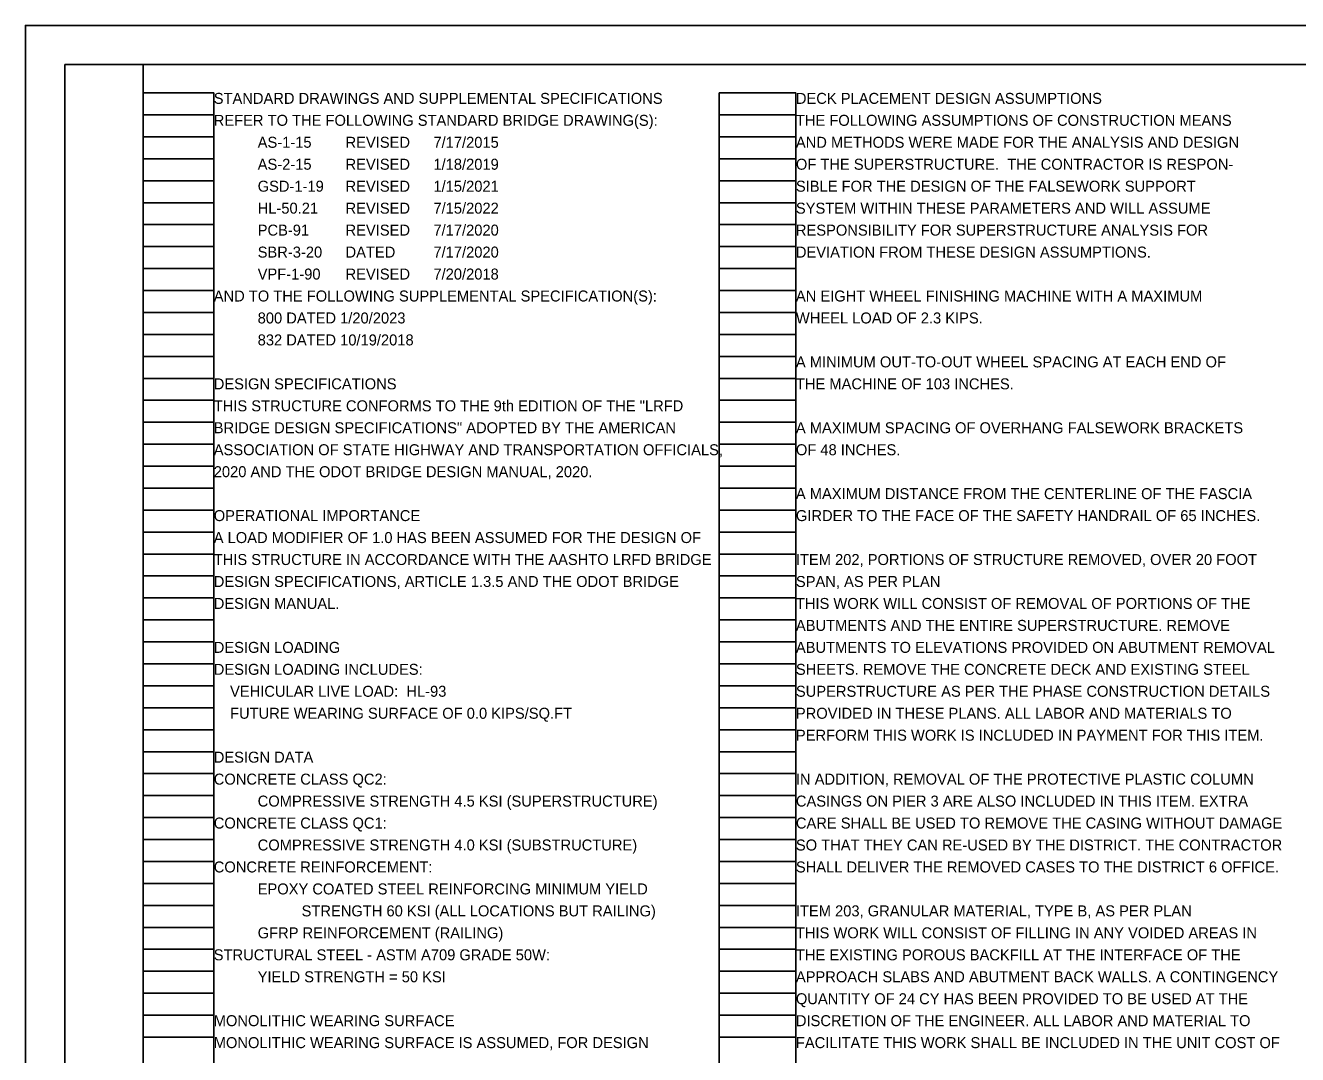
# Model space of a CAD drawing. Extents: x 0 to 56.6, y -19.6 to 22.
# Drawn here: x 0 to 16.21, y 8.88 to 22 of the extents above; entities that cross this region are included whole.
import ezdxf

# ---------------------------------------------------------------- set-up
doc = ezdxf.new("R2010")
doc.units = 0
for name, color, linetype in [('BR_P_Gen_Text', 7, 'Continuous'), ('SH_Border', 7, 'Continuous'), ('SH_Cut_Line', 7, 'Continuous'), ('SH_Data', 7, 'Continuous')]:
    doc.layers.add(name, color=color, linetype=linetype)

msp = doc.modelspace()

# ---------------------------------------------------------------- linework, layer by layer
at = {"layer": 'SH_Border'}
msp.add_lwpolyline([(0, 0), (34, 0), (34, 22), (0, 22)], close=True, dxfattribs=at)
at = {"layer": 'SH_Cut_Line'}
for points in [[(0.5, 21.5), (1.5, 21.5), (1.5, 0.5), (0.5, 0.5)], [(1.5, 21.5), (33.5, 21.5), (33.5, 0.5), (1.5, 0.5)]]:
    msp.add_lwpolyline(points, close=True, dxfattribs=at)
at = {"layer": 'SH_Data'}
for p, q in [((1.5, 0.98), (1.5, 21.14)), ((1.5, 21.14), (2.4, 21.14)), ((2.4, 0.98), (2.4, 21.14)), ((8.84, 0.98), (8.84, 21.14)), ((8.84, 21.14), (9.82, 21.14)), ((9.82, 0.98), (9.82, 21.14)), ((1.5, 20.86), (2.4, 20.86)), ((8.84, 20.86), (9.82, 20.86)), ((1.5, 20.58), (2.4, 20.58)), ((8.84, 20.58), (9.82, 20.58)), ((1.5, 20.3), (2.4, 20.3)), ((8.84, 20.3), (9.82, 20.3)), ((1.5, 20.02), (2.4, 20.02)), ((8.84, 20.02), (9.82, 20.02)), ((1.5, 19.74), (2.4, 19.74)), ((8.84, 19.74), (9.82, 19.74)), ((1.5, 19.46), (2.4, 19.46)), ((8.84, 19.46), (9.82, 19.46)), ((1.5, 19.18), (2.4, 19.18)), ((8.84, 19.18), (9.82, 19.18)), ((1.5, 18.9), (2.4, 18.9)), ((8.84, 18.9), (9.82, 18.9)), ((1.5, 18.62), (2.4, 18.62)), ((8.84, 18.62), (9.82, 18.62)), ((1.5, 18.34), (2.4, 18.34)), ((8.84, 18.34), (9.82, 18.34)), ((1.5, 18.06), (2.4, 18.06)), ((8.84, 18.06), (9.82, 18.06)), ((1.5, 17.78), (2.4, 17.78)), ((8.84, 17.78), (9.82, 17.78)), ((1.5, 17.5), (2.4, 17.5)), ((8.84, 17.5), (9.82, 17.5)), ((1.5, 17.22), (2.4, 17.22)), ((8.84, 17.22), (9.82, 17.22)), ((1.5, 16.94), (2.4, 16.94)), ((8.84, 16.94), (9.82, 16.94)), ((1.5, 16.66), (2.4, 16.66)), ((8.84, 16.66), (9.82, 16.66)), ((1.5, 16.38), (2.4, 16.38)), ((8.84, 16.38), (9.82, 16.38)), ((1.5, 16.1), (2.4, 16.1)), ((8.84, 16.1), (9.82, 16.1)), ((1.5, 15.82), (2.4, 15.82)), ((8.84, 15.82), (9.82, 15.82)), ((1.5, 15.54), (2.4, 15.54)), ((8.84, 15.54), (9.82, 15.54)), ((1.5, 15.26), (2.4, 15.26)), ((8.84, 15.26), (9.82, 15.26)), ((1.5, 14.98), (2.4, 14.98)), ((8.84, 14.98), (9.82, 14.98)), ((1.5, 14.7), (2.4, 14.7)), ((8.84, 14.7), (9.82, 14.7)), ((1.5, 14.42), (2.4, 14.42)), ((8.84, 14.42), (9.82, 14.42)), ((1.5, 14.14), (2.4, 14.14)), ((8.84, 14.14), (9.82, 14.14)), ((1.5, 13.86), (2.4, 13.86)), ((8.84, 13.86), (9.82, 13.86)), ((1.5, 13.58), (2.4, 13.58)), ((8.84, 13.58), (9.82, 13.58)), ((1.5, 13.3), (2.4, 13.3)), ((8.84, 13.3), (9.82, 13.3)), ((1.5, 13.02), (2.4, 13.02)), ((8.84, 13.02), (9.82, 13.02)), ((1.5, 12.74), (2.4, 12.74)), ((8.84, 12.74), (9.82, 12.74)), ((1.5, 12.46), (2.4, 12.46)), ((8.84, 12.46), (9.82, 12.46)), ((1.5, 12.18), (2.4, 12.18)), ((8.84, 12.18), (9.82, 12.18)), ((1.5, 11.9), (2.4, 11.9)), ((8.84, 11.9), (9.82, 11.9)), ((1.5, 11.62), (2.4, 11.62)), ((8.84, 11.62), (9.82, 11.62)), ((1.5, 11.34), (2.4, 11.34)), ((8.84, 11.34), (9.82, 11.34)), ((1.5, 11.06), (2.4, 11.06)), ((8.84, 11.06), (9.82, 11.06)), ((1.5, 10.78), (2.4, 10.78)), ((8.84, 10.78), (9.82, 10.78)), ((1.5, 10.5), (2.4, 10.5)), ((8.84, 10.5), (9.82, 10.5)), ((1.5, 10.22), (2.4, 10.22)), ((8.84, 10.22), (9.82, 10.22)), ((1.5, 9.94), (2.4, 9.94)), ((8.84, 9.94), (9.82, 9.94)), ((1.5, 9.66), (2.4, 9.66)), ((8.84, 9.66), (9.82, 9.66)), ((1.5, 9.38), (2.4, 9.38)), ((8.84, 9.38), (9.82, 9.38)), ((1.5, 9.1), (2.4, 9.1)), ((8.84, 9.1), (9.82, 9.1))]:
    msp.add_line(p, q, dxfattribs=at)

# ---------------------------------------------------------------- texts
at = {"layer": 'BR_P_Gen_Text'}
for s, p in [('STANDARD DRAWINGS AND SUPPLEMENTAL SPECIFICATIONS', (2.4, 21)), ('DECK PLACEMENT DESIGN ASSUMPTIONS', (9.82, 21)), ('REFER TO THE FOLLOWING STANDARD BRIDGE DRAWING(S):', (2.4, 20.72)), ('THE FOLLOWING ASSUMPTIONS OF CONSTRUCTION MEANS', (9.82, 20.72)), ('AS-1-15', (2.96, 20.44)), ('REVISED', (4.08, 20.44)), ('7/17/2015', (5.2, 20.44)), ('AND METHODS WERE MADE FOR THE ANALYSIS AND DESIGN', (9.82, 20.44)), ('AS-2-15', (2.96, 20.16)), ('REVISED', (4.08, 20.16)), ('1/18/2019', (5.2, 20.16)), ('OF THE SUPERSTRUCTURE.  THE CONTRACTOR IS RESPON-', (9.82, 20.16)), ('GSD-1-19', (2.96, 19.88)), ('REVISED', (4.08, 19.88)), ('1/15/2021', (5.2, 19.88)), ('SIBLE FOR THE DESIGN OF THE FALSEWORK SUPPORT', (9.82, 19.88)), ('HL-50.21', (2.96, 19.6)), ('REVISED', (4.08, 19.6)), ('7/15/2022', (5.2, 19.6)), ('SYSTEM WITHIN THESE PARAMETERS AND WILL ASSUME', (9.82, 19.6)), ('PCB-91', (2.96, 19.32)), ('REVISED', (4.08, 19.32)), ('7/17/2020', (5.2, 19.32)), ('RESPONSIBILITY FOR SUPERSTRUCTURE ANALYSIS FOR', (9.82, 19.32)), ('SBR-3-20', (2.96, 19.04)), ('DATED', (4.08, 19.04)), ('7/17/2020', (5.2, 19.04)), ('DEVIATION FROM THESE DESIGN ASSUMPTIONS.', (9.82, 19.04)), ('VPF-1-90', (2.96, 18.76)), ('REVISED', (4.08, 18.76)), ('7/20/2018', (5.2, 18.76)), ('AND TO THE FOLLOWING SUPPLEMENTAL SPECIFICATION(S):', (2.4, 18.48)), ('AN EIGHT WHEEL FINISHING MACHINE WITH A MAXIMUM', (9.82, 18.48)), ('800 DATED 1/20/2023', (2.96, 18.2)), ('WHEEL LOAD OF 2.3 KIPS.', (9.82, 18.2)), ('832 DATED 10/19/2018', (2.96, 17.92)), ('A MINIMUM OUT-TO-OUT WHEEL SPACING AT EACH END OF', (9.82, 17.64)), ('DESIGN SPECIFICATIONS', (2.4, 17.36)), ('THE MACHINE OF 103 INCHES.', (9.82, 17.36)), ('THIS STRUCTURE CONFORMS TO THE 9th EDITION OF THE "LRFD ', (2.4, 17.08)), ('BRIDGE DESIGN SPECIFICATIONS" ADOPTED BY THE AMERICAN ', (2.4, 16.8)), ('A MAXIMUM SPACING OF OVERHANG FALSEWORK BRACKETS', (9.82, 16.8)), ('ASSOCIATION OF STATE HIGHWAY AND TRANSPORTATION OFFICIALS, ', (2.4, 16.52)), ('OF 48 INCHES.', (9.82, 16.52)), ('2020 AND THE ODOT BRIDGE DESIGN MANUAL, 2020.', (2.4, 16.24)), ('A MAXIMUM DISTANCE FROM THE CENTERLINE OF THE FASCIA ', (9.82, 15.96)), ('OPERATIONAL IMPORTANCE', (2.4, 15.68)), ('GIRDER TO THE FACE OF THE SAFETY HANDRAIL OF 65 INCHES.', (9.82, 15.68)), ('A LOAD MODIFIER OF 1.0 HAS BEEN ASSUMED FOR THE DESIGN OF ', (2.4, 15.4)), ('THIS STRUCTURE IN ACCORDANCE WITH THE AASHTO LRFD BRIDGE ', (2.4, 15.12)), ('ITEM 202, PORTIONS OF STRUCTURE REMOVED, OVER 20 FOOT', (9.82, 15.12)), ('DESIGN SPECIFICATIONS, ARTICLE 1.3.5 AND THE ODOT BRIDGE ', (2.4, 14.84)), ('SPAN, AS PER PLAN', (9.82, 14.84)), ('DESIGN MANUAL.', (2.4, 14.56)), ('THIS WORK WILL CONSIST OF REMOVAL OF PORTIONS OF THE ', (9.82, 14.56)), ('ABUTMENTS AND THE ENTIRE SUPERSTRUCTURE. REMOVE ', (9.82, 14.28)), ('DESIGN LOADING', (2.4, 14)), ('ABUTMENTS TO ELEVATIONS PROVIDED ON ABUTMENT REMOVAL ', (9.82, 14)), ('DESIGN LOADING INCLUDES:', (2.4, 13.72)), ('SHEETS. REMOVE THE CONCRETE DECK AND EXISTING STEEL ', (9.82, 13.72)), ('    VEHICULAR LIVE LOAD:  HL-93', (2.4, 13.44)), ('SUPERSTRUCTURE AS PER THE PHASE CONSTRUCTION DETAILS ', (9.82, 13.44)), ('    FUTURE WEARING SURFACE OF 0.0 KIPS/SQ.FT', (2.4, 13.16)), ('PROVIDED IN THESE PLANS. ALL LABOR AND MATERIALS TO ', (9.82, 13.16)), ('PERFORM THIS WORK IS INCLUDED IN PAYMENT FOR THIS ITEM.', (9.82, 12.88)), ('DESIGN DATA', (2.4, 12.6)), ('CONCRETE CLASS QC2:', (2.4, 12.32)), ('IN ADDITION, REMOVAL OF THE PROTECTIVE PLASTIC COLUMN ', (9.82, 12.32)), ('COMPRESSIVE STRENGTH 4.5 KSI (SUPERSTRUCTURE)', (2.96, 12.04)), ('CASINGS ON PIER 3 ARE ALSO INCLUDED IN THIS ITEM. EXTRA ', (9.82, 12.04)), ('CONCRETE CLASS QC1:', (2.4, 11.76)), ('CARE SHALL BE USED TO REMOVE THE CASING WITHOUT DAMAGE ', (9.82, 11.76)), ('COMPRESSIVE STRENGTH 4.0 KSI (SUBSTRUCTURE)', (2.96, 11.48)), ('SO THAT THEY CAN RE-USED BY THE DISTRICT. THE CONTRACTOR ', (9.82, 11.48)), ('CONCRETE REINFORCEMENT:', (2.4, 11.2)), ('SHALL DELIVER THE REMOVED CASES TO THE DISTRICT 6 OFFICE.', (9.82, 11.2)), ('EPOXY COATED STEEL REINFORCING MINIMUM YIELD ', (2.96, 10.92)), ('STRENGTH 60 KSI (ALL LOCATIONS BUT RAILING)', (3.52, 10.64)), ('ITEM 203, GRANULAR MATERIAL, TYPE B, AS PER PLAN', (9.82, 10.64)), ('GFRP REINFORCEMENT (RAILING)', (2.96, 10.36)), ('THIS WORK WILL CONSIST OF FILLING IN ANY VOIDED AREAS IN ', (9.82, 10.36)), ('STRUCTURAL STEEL - ASTM A709 GRADE 50W:', (2.4, 10.08)), ('THE EXISTING POROUS BACKFILL AT THE INTERFACE OF THE ', (9.82, 10.08)), ('YIELD STRENGTH = 50 KSI', (2.96, 9.8)), ('APPROACH SLABS AND ABUTMENT BACK WALLS. A CONTINGENCY ', (9.82, 9.8)), ('QUANTITY OF 24 CY HAS BEEN PROVIDED TO BE USED AT THE ', (9.82, 9.52)), ('MONOLITHIC WEARING SURFACE', (2.4, 9.24)), ('DISCRETION OF THE ENGINEER. ALL LABOR AND MATERIAL TO ', (9.82, 9.24)), ('MONOLITHIC WEARING SURFACE IS ASSUMED, FOR DESIGN', (2.4, 8.96)), ('FACILITATE THIS WORK SHALL BE INCLUDED IN THE UNIT COST OF ', (9.82, 8.96))]:
    msp.add_text(s, height=0.14, dxfattribs=at).set_placement(p)

doc.saveas('drawing.dxf')
